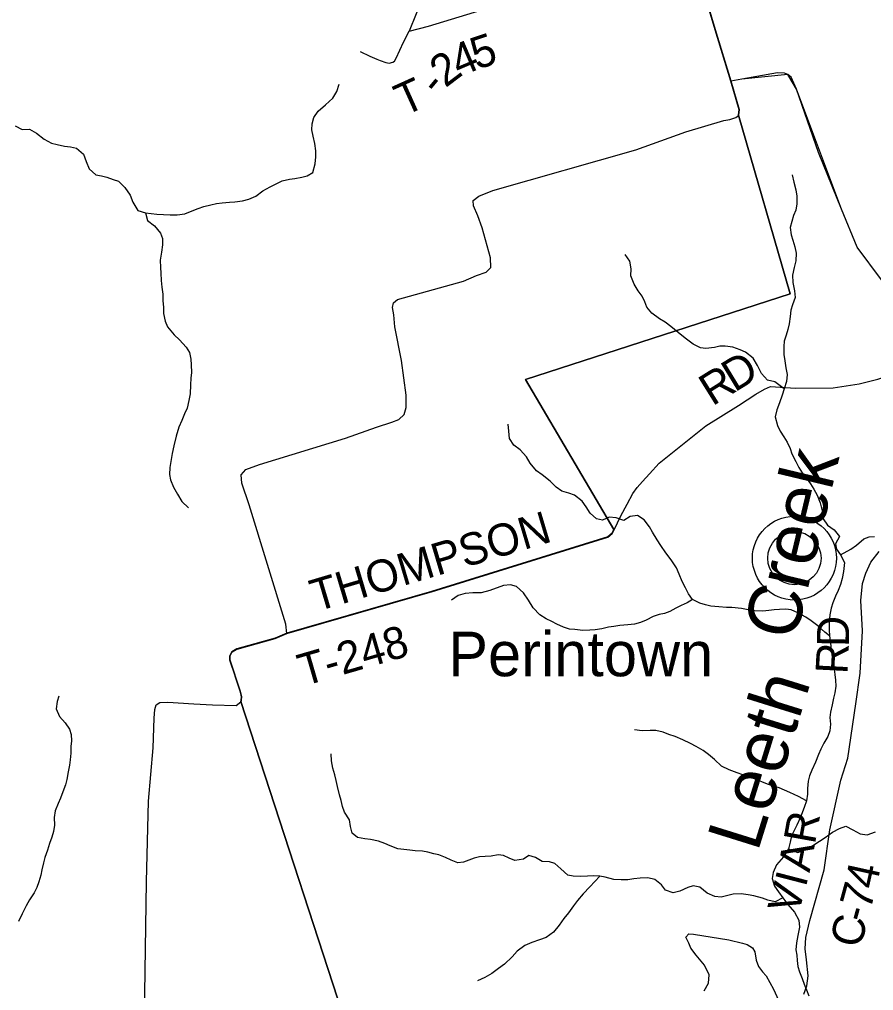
# Model space of a CAD drawing. Extents: x 0 to 34, y 0 to 22.
# Drawn here: x 3.486 to 5.001, y 15.038 to 16.76 of the extents above; entities that cross this region are included whole.
import ezdxf

# ---------------------------------------------------------------- set-up
doc = ezdxf.new("R2010")
doc.units = 0
for name, color, linetype in [('Default', 7, 'Continuous'), ('GM_X_County_Road', 7, 'Continuous'), ('GM_X_County_Road_Text', 7, 'Continuous'), ('GM_X_Minor_River', 7, 'Continuous'), ('GM_X_Minor_River_Text', 7, 'Continuous'), ('GM_X_State_Route', 7, 'Continuous'), ('GM_X_Township_Road', 7, 'Continuous'), ('GM_X_Township_Road_Text', 7, 'Continuous'), ('GM_X_Unincorporated', 7, 'Continuous'), ('GM_X_Unincorporated_Location', 7, 'Continuous'), ('GM_X_Unincorporated_Text', 7, 'Continuous')]:
    doc.layers.add(name, color=color, linetype=linetype)

msp = doc.modelspace()

# ---------------------------------------------------------------- linework, layer by layer
at = {"layer": 'Default'}
for p, q in [((4.7196, 16.7418), (4.676, 16.8898)), ((4.7475, 16.6508), (4.7196, 16.7418)), ((4.7669, 16.6542), (4.7475, 16.6508)), ((4.8483, 16.6622), (4.7669, 16.6542)), ((4.8641, 16.6365), (4.8483, 16.6622)), ((4.9435, 16.4238), (4.8641, 16.6365)), ((4.9717, 16.3565), (4.9435, 16.4238)), ((5.0144, 16.2982), (4.9717, 16.3565))]:
    msp.add_line(p, q, dxfattribs=at)
for points in [[(4.6758, 16.8903), (4.7194, 16.7424), (4.7473, 16.6513), (4.7621, 16.6005), (4.7609, 16.5903), (4.8529, 16.2733), (4.3836, 16.1215), (4.5402, 15.8556), (4.5368, 15.8488), (4.5292, 15.8423), (4.2168, 15.7459), (3.9602, 15.6717), (3.9395, 15.6629), (3.8718, 15.6439), (3.8625, 15.6385), (3.8592, 15.6307), (3.8592, 15.6242), (3.8777, 15.5687), (3.8797, 15.5595), (3.8795, 15.5524), (3.8786, 15.5505), (4.0933, 14.8918)], [(4.0933, 14.8918), (3.8786, 15.5505), (3.8795, 15.5524), (3.8797, 15.5595), (3.8777, 15.5687), (3.8592, 15.6242), (3.8592, 15.6307), (3.8625, 15.6385), (3.8718, 15.6439), (3.9395, 15.6629), (3.9602, 15.6717), (4.2168, 15.7459), (4.5292, 15.8423), (4.5368, 15.8488), (4.5402, 15.8556), (4.3836, 16.1215), (4.8529, 16.2733), (4.7609, 16.5903), (4.7621, 16.6005), (4.7473, 16.6513), (4.7194, 16.7424), (4.6758, 16.8903)]]:
    msp.add_lwpolyline(points, dxfattribs=at)
at = {"layer": 'GM_X_County_Road'}
for points in [[(4.7563, 16.5863), (4.7611, 16.5898), (4.7624, 16.6), (4.7475, 16.6508)], [(3.9604, 15.6712), (3.9585, 15.6877), (3.8933, 15.8996), (3.8806, 15.9376), (3.8792, 15.9524), (3.8877, 15.9622), (3.9115, 15.9708), (4.0644, 16.0177), (4.1194, 16.0372), (4.1464, 16.046), (4.1589, 16.0508), (4.1685, 16.0594), (4.1716, 16.0719), (4.1719, 16.0939), (4.1638, 16.1551), (4.152, 16.2152), (4.1499, 16.2361), (4.1478, 16.2494), (4.1494, 16.2578), (4.1567, 16.2634), (4.2735, 16.2959), (4.2963, 16.3059), (4.3134, 16.3121), (4.3222, 16.3204), (4.3216, 16.3375), (4.3067, 16.3904), (4.299, 16.4121), (4.2912, 16.4297), (4.2909, 16.4388), (4.3008, 16.447), (4.3252, 16.4566), (4.5793, 16.5289), (4.6679, 16.561), (4.7351, 16.5808), (4.7459, 16.5826), (4.7563, 16.5863)], [(4.877, 15.0317), (4.8821, 15.0461), (4.8845, 15.0639), (4.8818, 15.0924), (4.8794, 15.1122), (4.8804, 15.1323), (4.8875, 15.1622), (4.9127, 15.2519), (4.9233, 15.3232), (4.9424, 15.411), (4.9549, 15.45), (4.9692, 15.5462), (4.9766, 15.6008), (4.9808, 15.6759), (4.978, 15.7295), (4.9809, 15.7598), (4.9868, 15.7784), (4.9957, 15.7976), (5.0103, 15.8165)], [(3.8799, 15.558), (3.8799, 15.559), (3.8779, 15.5682), (3.8594, 15.6237), (3.8594, 15.6302), (3.8627, 15.638), (3.872, 15.6434), (3.9397, 15.6624), (3.9604, 15.6712)], [(3.708, 14.9932), (3.7113, 15.2305), (3.7148, 15.3736), (3.7233, 15.4682), (3.7252, 15.5208), (3.7263, 15.5361), (3.7286, 15.5449), (3.7353, 15.5485), (3.7492, 15.5493), (3.7952, 15.5463), (3.8284, 15.5446), (3.8704, 15.5433), (3.8788, 15.55), (3.8798, 15.5519), (3.8799, 15.558)]]:
    msp.add_lwpolyline(points, dxfattribs=at)
at = {"layer": 'GM_X_Minor_River'}
for points in [[(3.9307, 16.4631), (3.9519, 16.4738), (3.9648, 16.4768), (3.9743, 16.4783), (3.9868, 16.4806), (3.9963, 16.4829), (4.0065, 16.4886), (4.0107, 16.5038), (4.0115, 16.5164), (4.0119, 16.5274), (4.0096, 16.5403), (4.007, 16.5532), (4.0047, 16.5643), (4.0051, 16.5749), (4.0081, 16.5863), (4.0157, 16.5973), (4.0286, 16.6087), (4.0415, 16.6205), (4.0487, 16.6323), (4.0529, 16.6456)], [(3.4783, 16.5712), (3.4908, 16.5651), (3.5037, 16.5658), (3.5166, 16.5582), (3.5302, 16.548), (3.5431, 16.5407), (3.5533, 16.5385), (3.5662, 16.5354), (3.5769, 16.5343), (3.5875, 16.5316), (3.5996, 16.521), (3.6045, 16.508), (3.6098, 16.4951), (3.6216, 16.4845), (3.6314, 16.4826), (3.6409, 16.4803), (3.6523, 16.4765), (3.6618, 16.4731), (3.6731, 16.462), (3.6826, 16.4487), (3.6872, 16.4362), (3.6963, 16.4213), (3.7099, 16.4172), (3.7296, 16.4149), (3.7418, 16.4141), (3.7531, 16.4137), (3.766, 16.4134), (3.7793, 16.4153), (3.7896, 16.4194), (3.8028, 16.4251), (3.8131, 16.4286), (3.8256, 16.4316), (3.8358, 16.4339), (3.8457, 16.435), (3.8586, 16.4362), (3.8681, 16.4369), (3.8814, 16.4384), (3.8927, 16.4415), (3.9053, 16.4468), (3.9178, 16.4559), (3.9307, 16.4631)], [(4.8561, 16.4843), (4.8592, 16.4718), (4.8626, 16.4581), (4.8645, 16.4467), (4.8644, 16.433), (4.8625, 16.422), (4.8587, 16.4124), (4.8527, 16.3912), (4.8546, 16.3782), (4.8576, 16.3687), (4.861, 16.3569), (4.8633, 16.3455), (4.8625, 16.3322), (4.8595, 16.3201), (4.8568, 16.3068), (4.8575, 16.2934), (4.8606, 16.279), (4.8617, 16.2668), (4.8571, 16.2543), (4.8537, 16.2444), (4.8526, 16.2334), (4.8511, 16.2201), (4.8488, 16.2102), (4.8454, 16.2003), (4.8419, 16.1897), (4.8412, 16.1802), (4.8415, 16.1657), (4.8431, 16.1547), (4.8449, 16.1425), (4.8472, 16.1303), (4.8461, 16.1182), (4.8423, 16.1053), (4.8385, 16.0938), (4.8339, 16.0805), (4.829, 16.0676), (4.8263, 16.0551), (4.8301, 16.0402), (4.835, 16.03), (4.8415, 16.0201), (4.8471, 16.0106), (4.8528, 15.9992), (4.8559, 15.9897), (4.8627, 15.976), (4.868, 15.9657), (4.874, 15.9562), (4.8816, 15.9467), (4.8885, 15.9368), (4.8949, 15.9269), (4.9006, 15.9167), (4.9059, 15.903), (4.9093, 15.8885), (4.9112, 15.8748), (4.9188, 15.863), (4.9309, 15.8551), (4.94, 15.8433), (4.9331, 15.83), (4.9347, 15.8205), (4.9422, 15.8106), (4.9491, 15.7973), (4.9475, 15.7809), (4.9449, 15.7688), (4.9418, 15.7581), (4.9377, 15.7475), (4.9331, 15.7372), (4.9282, 15.7258), (4.9251, 15.7163), (4.9228, 15.7041), (4.9217, 15.6904), (4.9221, 15.6775), (4.9224, 15.6672), (4.924, 15.6543), (4.9255, 15.6425), (4.9285, 15.6205), (4.9304, 15.6079), (4.9319, 15.5984), (4.933, 15.5882), (4.9334, 15.5779), (4.9319, 15.5661), (4.9296, 15.5566), (4.9269, 15.5448), (4.9243, 15.5315), (4.9231, 15.522), (4.9239, 15.5102), (4.9231, 15.4988), (4.9193, 15.4886), (4.9121, 15.4764), (4.9068, 15.4661), (4.903, 15.4566), (4.8973, 15.4429), (4.8908, 15.4285), (4.887, 15.4186), (4.8844, 15.4091), (4.8836, 15.3962), (4.8836, 15.3863), (4.8817, 15.3745), (4.8775, 15.3627), (4.8711, 15.3456), (4.8646, 15.3315), (4.8597, 15.3217), (4.8551, 15.3122), (4.8525, 15.3011)], [(3.7099, 16.4172), (3.7133, 16.4035), (3.7255, 16.394), (3.7364, 16.381), (3.7395, 16.3715), (3.7398, 16.3605), (3.7379, 16.3472), (3.7357, 16.3335), (3.736, 16.3202), (3.7368, 16.3099), (3.7375, 16.2974), (3.7387, 16.2852), (3.7402, 16.2731), (3.7405, 16.2617), (3.7413, 16.2491), (3.7417, 16.2388), (3.7443, 16.2248), (3.7489, 16.2149), (3.7602, 16.2008), (3.7697, 16.1917), (3.7818, 16.1792), (3.7875, 16.1696), (3.7902, 16.1575), (3.7905, 16.1476), (3.7909, 16.1343), (3.7902, 16.124), (3.7894, 16.1122), (3.7886, 16.0963), (3.7867, 16.0841), (3.7833, 16.0708), (3.7787, 16.0609), (3.7738, 16.0487), (3.7685, 16.037), (3.7639, 16.0214), (3.7597, 16.0039), (3.7571, 15.9906), (3.7525, 15.9655), (3.7521, 15.9533), (3.754, 15.9434), (3.759, 15.9305), (3.7665, 15.9183), (3.7741, 15.9054), (3.7859, 15.894)], [(4.8423, 16.1053), (4.8256, 16.1174), (4.8127, 16.1205), (4.8021, 16.1323), (4.7949, 16.1467), (4.7869, 16.1592), (4.7737, 16.1703), (4.7642, 16.1745), (4.7509, 16.179), (4.7376, 16.1809), (4.7281, 16.1805), (4.7183, 16.1786), (4.7031, 16.1768), (4.6936, 16.1779), (4.6807, 16.184), (4.6663, 16.195), (4.6542, 16.2049), (4.6413, 16.2155), (4.6311, 16.2231), (4.6212, 16.2292), (4.6072, 16.2391), (4.5988, 16.2498), (4.5947, 16.2596), (4.5905, 16.2692), (4.5833, 16.2787), (4.5761, 16.2908), (4.5701, 16.3053), (4.5708, 16.3178), (4.5682, 16.3315), (4.5602, 16.3433)], [(4.9224, 15.6672), (4.9141, 15.6733), (4.9016, 15.6847), (4.8898, 15.6935), (4.8804, 15.7), (4.8663, 15.7076), (4.8542, 15.7133), (4.8447, 15.7144), (4.8337, 15.7136), (4.8242, 15.7129), (4.8147, 15.7117), (4.8041, 15.711), (4.7893, 15.7114), (4.7783, 15.7133), (4.7662, 15.7156), (4.7495, 15.7175), (4.74, 15.7175), (4.7264, 15.7182), (4.7123, 15.7194), (4.7025, 15.7217), (4.6926, 15.7247), (4.6797, 15.7312), (4.6725, 15.7414), (4.6669, 15.7521), (4.6612, 15.7635), (4.6559, 15.7764), (4.6509, 15.7874), (4.6415, 15.8019), (4.632, 15.8144), (4.6233, 15.827), (4.6168, 15.8372), (4.6085, 15.8509), (4.6032, 15.8604), (4.5941, 15.8726), (4.582, 15.8806), (4.5687, 15.8787), (4.5577, 15.8715), (4.5444, 15.876), (4.5319, 15.8772), (4.5198, 15.8719), (4.5091, 15.8745), (4.4978, 15.8844), (4.4909, 15.8958), (4.4841, 15.9061), (4.4705, 15.9167), (4.4602, 15.9198), (4.4477, 15.9236), (4.4379, 15.9308), (4.4269, 15.9411), (4.4128, 15.9525), (4.403, 15.9597), (4.3916, 15.973), (4.3852, 15.9844), (4.3742, 15.9966), (4.3628, 16.0049), (4.3548, 16.0171), (4.3537, 16.03), (4.3526, 16.0422)], [(4.9422, 15.8106), (4.9605, 15.8205), (4.9703, 15.8281), (4.9832, 15.8391), (4.9927, 15.8425), (5.0022, 15.8433)], [(4.6797, 15.7312), (4.6699, 15.7258), (4.6596, 15.7209), (4.6498, 15.716), (4.6395, 15.7099), (4.63, 15.7068), (4.6206, 15.7046), (4.6096, 15.7011), (4.5974, 15.6947), (4.5872, 15.6905), (4.5765, 15.6875), (4.5648, 15.6867), (4.5508, 15.6856), (4.5398, 15.6837), (4.5303, 15.6821), (4.5185, 15.6795), (4.5071, 15.6776), (4.4973, 15.6768), (4.4851, 15.6764), (4.4711, 15.678), (4.4612, 15.6791), (4.451, 15.6825), (4.4392, 15.6879), (4.4298, 15.6924), (4.4203, 15.6974), (4.4089, 15.7042), (4.3968, 15.7168), (4.3888, 15.7304), (4.3801, 15.743), (4.3672, 15.7544), (4.357, 15.7574), (4.3445, 15.7563), (4.3202, 15.7472), (4.305, 15.743), (4.2898, 15.743), (4.2762, 15.7422), (4.264, 15.7384), (4.2519, 15.7301)], [(3.5562, 15.5598), (3.5528, 15.5503), (3.5513, 15.5374), (3.557, 15.5241), (3.5672, 15.5127), (3.5748, 15.5013), (3.5778, 15.4918), (3.5786, 15.4811), (3.5774, 15.4709), (3.577, 15.4587), (3.5759, 15.4473), (3.5747, 15.4374), (3.5728, 15.426), (3.5702, 15.4123), (3.5675, 15.4028), (3.563, 15.3903), (3.5588, 15.3789), (3.555, 15.3694), (3.5497, 15.3564), (3.5474, 15.345), (3.5481, 15.331), (3.5466, 15.3203), (3.5436, 15.3097), (3.5394, 15.2986), (3.5356, 15.2869), (3.5314, 15.2739), (3.5288, 15.2644), (3.5261, 15.2523), (3.5242, 15.2428), (3.5204, 15.2306), (3.517, 15.2207), (3.5124, 15.2112), (3.5041, 15.1987), (3.498, 15.188), (3.4912, 15.1743), (3.4843, 15.1603)], [(4.8817, 15.3745), (4.8677, 15.3821), (4.8521, 15.3889), (4.8426, 15.3935), (4.8332, 15.3977), (4.8233, 15.4007), (4.8123, 15.4042), (4.7896, 15.4133), (4.7786, 15.4167), (4.7687, 15.4205), (4.7588, 15.4239), (4.7444, 15.4296), (4.7308, 15.4361), (4.7183, 15.4479), (4.708, 15.4563), (4.6982, 15.4635), (4.686, 15.4707), (4.6758, 15.476), (4.6622, 15.4825), (4.6485, 15.4882), (4.6375, 15.492), (4.6273, 15.4962), (4.6144, 15.4989), (4.6045, 15.4992), (4.5905, 15.4985), (4.5768, 15.5004)], [(4.8399, 15.2023), (4.8259, 15.1951), (4.8133, 15.1985), (4.8035, 15.2015), (4.7883, 15.2057), (4.7781, 15.208), (4.7656, 15.2095), (4.7515, 15.2091), (4.742, 15.2065), (4.7303, 15.2038), (4.7189, 15.205), (4.7056, 15.2107), (4.6927, 15.2213), (4.6806, 15.2236), (4.6711, 15.2209), (4.6571, 15.2141), (4.6453, 15.211), (4.6317, 15.216), (4.6245, 15.2255), (4.6127, 15.235), (4.6006, 15.2377), (4.5869, 15.2373), (4.5755, 15.2358), (4.5649, 15.2346), (4.5528, 15.2343), (4.5399, 15.235), (4.5247, 15.2388), (4.5152, 15.2411), (4.5031, 15.2415), (4.4936, 15.2407), (4.4803, 15.24), (4.4678, 15.2407), (4.4584, 15.2423), (4.4462, 15.2537), (4.4352, 15.2632), (4.4257, 15.2662), (4.4132, 15.2666), (4.4011, 15.2742), (4.3893, 15.2776), (4.3799, 15.2712), (4.3647, 15.2685), (4.3544, 15.2727), (4.3446, 15.2773), (4.3351, 15.2788), (4.3226, 15.2761), (4.312, 15.2754), (4.3021, 15.275), (4.2926, 15.2727), (4.2831, 15.2689), (4.2737, 15.2659), (4.2634, 15.2647), (4.2517, 15.2693), (4.2414, 15.2742), (4.23, 15.2784), (4.2206, 15.2807), (4.2103, 15.2834), (4.2005, 15.2849), (4.1876, 15.2856), (4.1781, 15.2868), (4.1675, 15.2879), (4.1572, 15.2894), (4.1436, 15.2944), (4.1341, 15.299), (4.1227, 15.3031), (4.1083, 15.3058), (4.0984, 15.3069), (4.0856, 15.3096), (4.0761, 15.3168), (4.073, 15.329), (4.0715, 15.3408), (4.0624, 15.3541), (4.0587, 15.3644), (4.0564, 15.375), (4.0537, 15.3853), (4.0503, 15.3997), (4.0477, 15.4107), (4.0454, 15.4206), (4.042, 15.4324), (4.0394, 15.4453), (4.0386, 15.4575)], [(4.8498, 15.2893), (4.8665, 15.2825), (4.8767, 15.2867), (4.8908, 15.2943), (4.9048, 15.3026), (4.9147, 15.3091), (4.9279, 15.3186), (4.9401, 15.3254), (4.9515, 15.3292), (4.964, 15.3232), (4.9769, 15.3156), (4.9894, 15.314), (5.0042, 15.3197)], [(4.8525, 15.3011), (4.8498, 15.2893), (4.8407, 15.2753), (4.8282, 15.2608), (4.8225, 15.2471), (4.8206, 15.2369), (4.8247, 15.2232), (4.8319, 15.2129), (4.8399, 15.2023), (4.8486, 15.1905), (4.8604, 15.1768), (4.8679, 15.1627), (4.8694, 15.1502), (4.866, 15.1354), (4.8637, 15.1228), (4.863, 15.1103), (4.8645, 15.1008), (4.8652, 15.0913), (4.8664, 15.0806), (4.8694, 15.0711), (4.8739, 15.0593), (4.8774, 15.049), (4.8815, 15.0392), (4.8857, 15.0285)], [(4.5152, 15.2411), (4.4974, 15.2221), (4.4856, 15.2092), (4.4758, 15.1978), (4.4686, 15.1883), (4.4595, 15.1757), (4.4515, 15.1655), (4.4431, 15.154), (4.4329, 15.1415), (4.42, 15.132), (4.4082, 15.1278), (4.3946, 15.1229), (4.382, 15.1176), (4.3684, 15.1077), (4.36, 15.0978), (4.3464, 15.0849), (4.3358, 15.0769), (4.324, 15.0681), (4.3115, 15.0613), (4.2982, 15.0552)]]:
    msp.add_lwpolyline(points, dxfattribs=at)
at = {"layer": 'GM_X_State_Route'}
for points in [[(4.7669, 16.6542), (4.7475, 16.6508), (4.7196, 16.7418), (4.676, 16.8898)], [(5.0144, 16.2982), (4.9717, 16.3565), (4.9435, 16.4238), (4.9028, 16.5239), (4.8641, 16.6365), (4.8542, 16.6575), (4.8483, 16.6622), (4.8424, 16.6647), (4.8302, 16.6654), (4.7669, 16.6542)]]:
    msp.add_lwpolyline(points, dxfattribs=at)
at = {"layer": 'GM_X_Township_Road'}
msp.add_line((3.9604, 15.6712), (4.2142, 15.7445), dxfattribs=at)
for points in [[(4.1773, 16.7396), (4.2115, 16.7483), (4.3943, 16.8043), (4.5306, 16.8465), (4.676, 16.8898)], [(4.1603, 16.8269), (4.1631, 16.8259), (4.1718, 16.8228), (4.1808, 16.8189), (4.1895, 16.8142), (4.1928, 16.8108), (4.1989, 16.8077), (4.2018, 16.8008), (4.1894, 16.7702), (4.1773, 16.7396)], [(4.09, 16.7034), (4.1076, 16.6952), (4.1201, 16.6897), (4.1257, 16.6874), (4.1359, 16.6835), (4.1415, 16.6827), (4.1484, 16.6845), (4.151, 16.686), (4.1541, 16.6916), (4.1673, 16.7196), (4.1773, 16.7396)], [(4.5464, 15.8674), (4.5524, 15.8796), (4.5638, 15.9007), (4.5736, 15.9192), (4.5815, 15.9299), (4.5907, 15.9408), (4.603, 15.9543), (4.6206, 15.9731), (4.703, 16.0397), (4.7609, 16.0755), (4.7917, 16.0953), (4.8069, 16.1042), (4.8179, 16.109), (4.8622, 16.1063), (4.9287, 16.107), (4.9749, 16.1141), (5.0079, 16.1221), (5.036, 16.1313), (5.0581, 16.1447), (5.0825, 16.1664), (5.1003, 16.1837)], [(4.2142, 15.7445), (4.217, 15.7453), (4.5294, 15.8417), (4.5371, 15.8483), (4.5404, 15.8551), (4.5464, 15.8674)], [(4.7, 15.0374), (4.7077, 15.051), (4.709, 15.0658), (4.7005, 15.083), (4.6859, 15.1007), (4.6765, 15.1133), (4.6728, 15.1221), (4.6676, 15.1328), (4.673, 15.1384), (4.681, 15.138), (4.7438, 15.1277), (4.768, 15.1221), (4.7767, 15.1194), (4.7857, 15.114), (4.7898, 15.1067), (4.7923, 15.0918), (4.7967, 15.0808), (4.8038, 15.0712), (4.8102, 15.0639), (4.8232, 15.0402), (4.8321, 15.0211)]]:
    msp.add_lwpolyline(points, dxfattribs=at)
at = {"layer": 'GM_X_Unincorporated'}
for radius in [0.0744, 0.0472]:
    msp.add_circle((4.8602, 15.8048), radius, dxfattribs=at)
at = {"layer": 'GM_X_Unincorporated_Location'}
msp.add_line((4.8602, 15.8048), (4.8602, 15.8048), dxfattribs=at)

# ---------------------------------------------------------------- texts
at = {"layer": 'GM_X_County_Road_Text'}
for s, rotation, p in [('D', 89.1924, (4.9567, 15.6471)), ('R', 87.1027, (4.9542, 15.5983)), ('R', 79.7964, (4.8965, 15.2959)), ('A', 79.1258, (4.8869, 15.2461)), ('4', 77.5821, (5.0045, 15.2158)), ('I', 75.4397, (4.8802, 15.2196)), ('V', 74.611, (4.8667, 15.1705)), ('7', 74.6564, (4.9945, 15.1789)), ('-', 74.521, (4.9883, 15.1563)), ('C', 77.0656, (4.978, 15.1115))]:
    msp.add_text(s, height=0.0568, rotation=rotation, dxfattribs=at).set_placement(p)
at = {"layer": 'GM_X_Minor_River_Text'}
for s, rotation, p in [('Creek', 76.5305, (4.8616, 15.656)), ('Leeth', 72.666, (4.7949, 15.282))]:
    msp.add_text(s, height=0.09471, rotation=rotation, dxfattribs=at).set_placement(p)
at = {"layer": 'GM_X_Township_Road_Text'}
for s, height, rotation, p in [('5', 0.0568, 18.3543, (4.2971, 16.6705)), ('4', 0.0568, 23.0346, (4.266, 16.6572)), ('2', 0.0568, 37.2529, (4.2413, 16.6379)), ('T', 0.0568, 24.2914, (4.168, 16.5881)), ('-', 0.0568, 50.0875, (4.2288, 16.6223)), ('D', 0.0568, 31.398, (4.7541, 16.0982)), ('R', 0.0568, 32.0033, (4.7147, 16.0735)), ('THOMPSON', 0.05682, 16.5925, (4.0121, 15.7094)), ('T-248', 0.05682, 16.2148, (3.9899, 15.5774))]:
    msp.add_text(s, height=height, rotation=rotation, dxfattribs=at).set_placement(p)
at = {"layer": 'GM_X_Unincorporated_Text'}
msp.add_text('Perintown', height=0.07898, rotation=0, dxfattribs=at).set_placement((4.2465, 15.5954))

doc.saveas('drawing.dxf')
